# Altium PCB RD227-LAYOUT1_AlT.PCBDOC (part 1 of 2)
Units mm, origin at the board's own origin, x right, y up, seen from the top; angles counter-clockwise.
Board outline 90 x 40 mm, 4 copper layers (TOP, Mid-Layer 1, Mid-Layer 2, BOTTOM), stack 0.711 mm thick; 157 components, 70 nets, 392 pads, 454 vias.
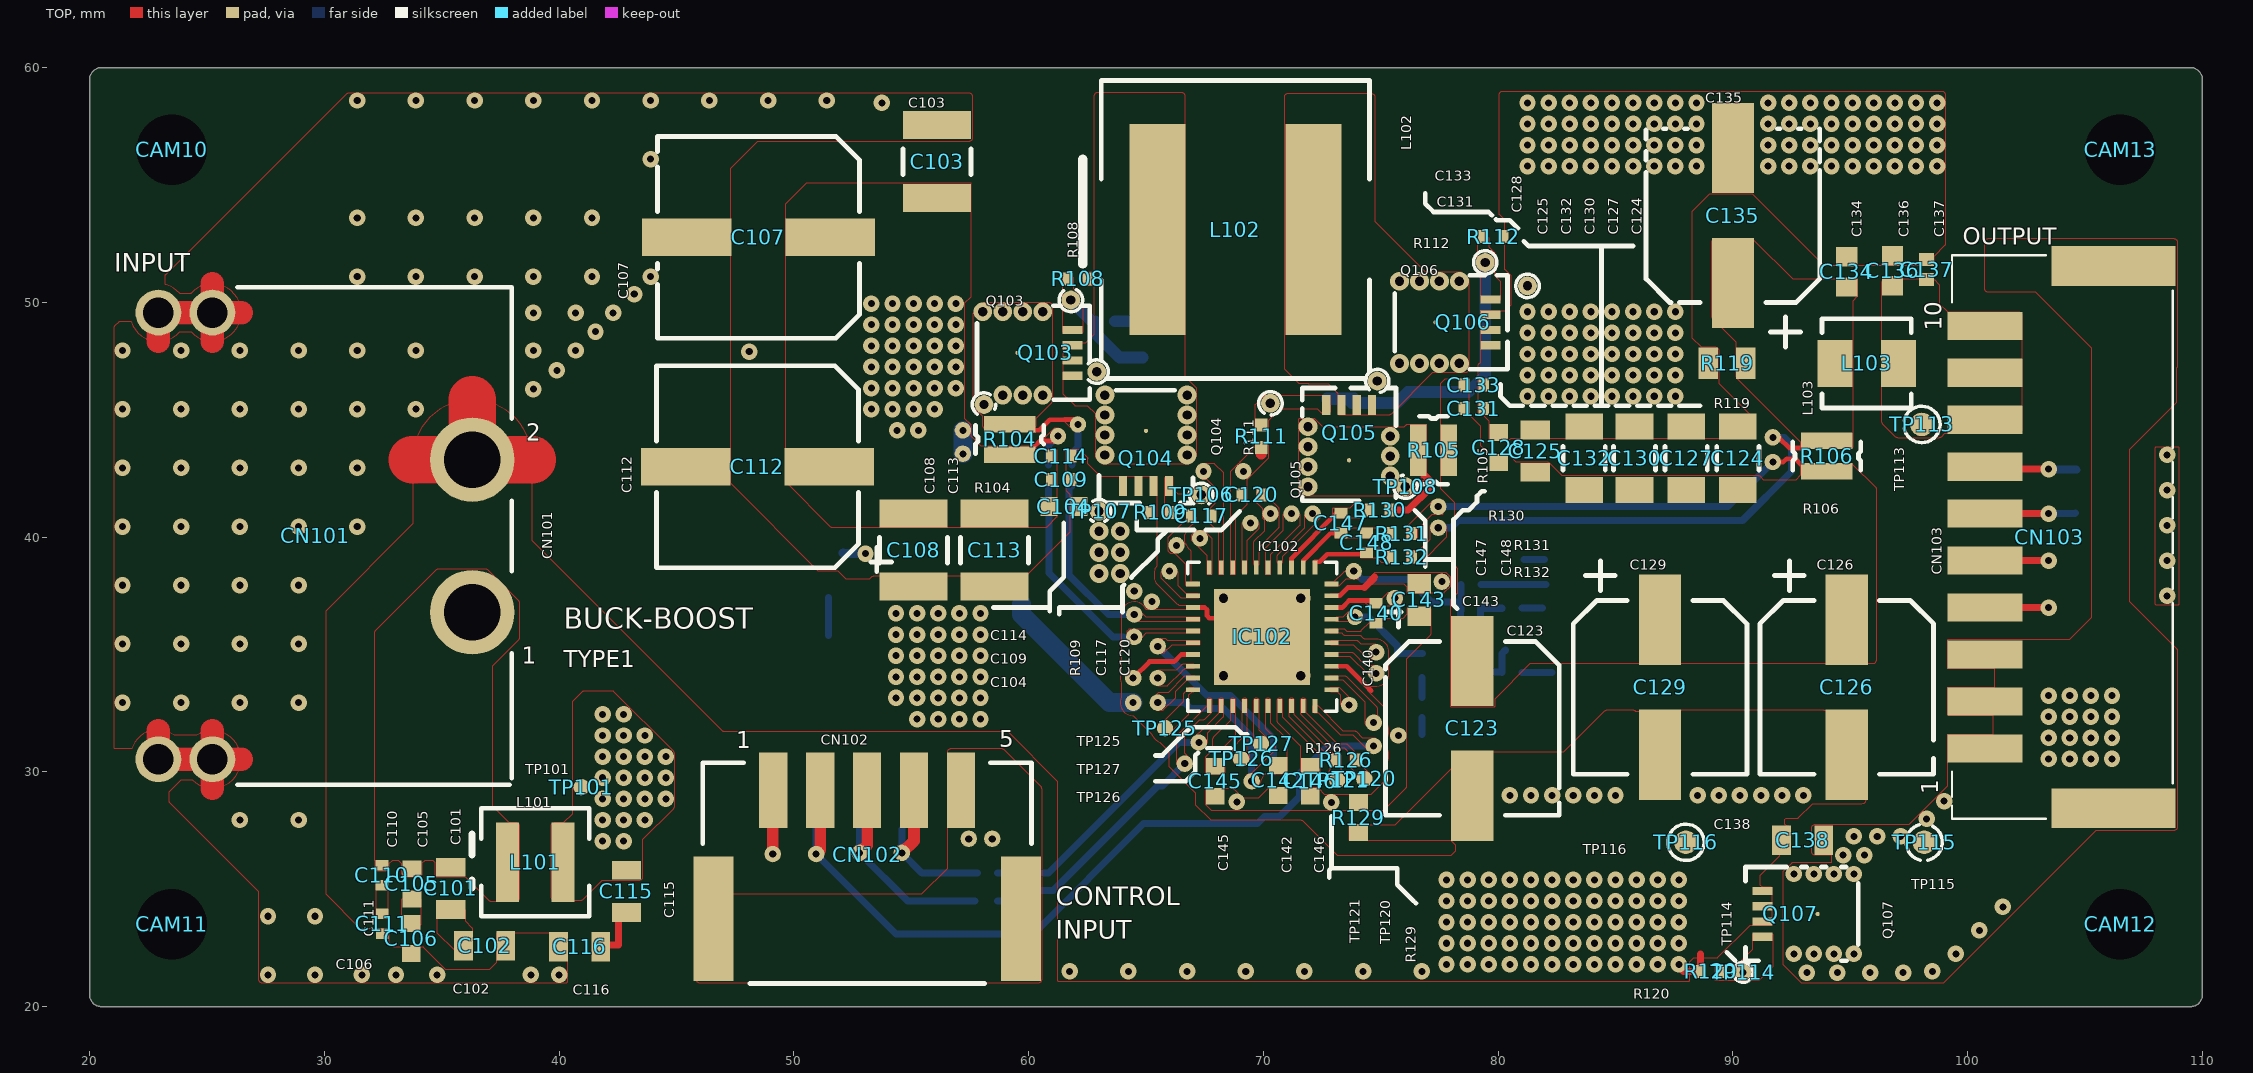
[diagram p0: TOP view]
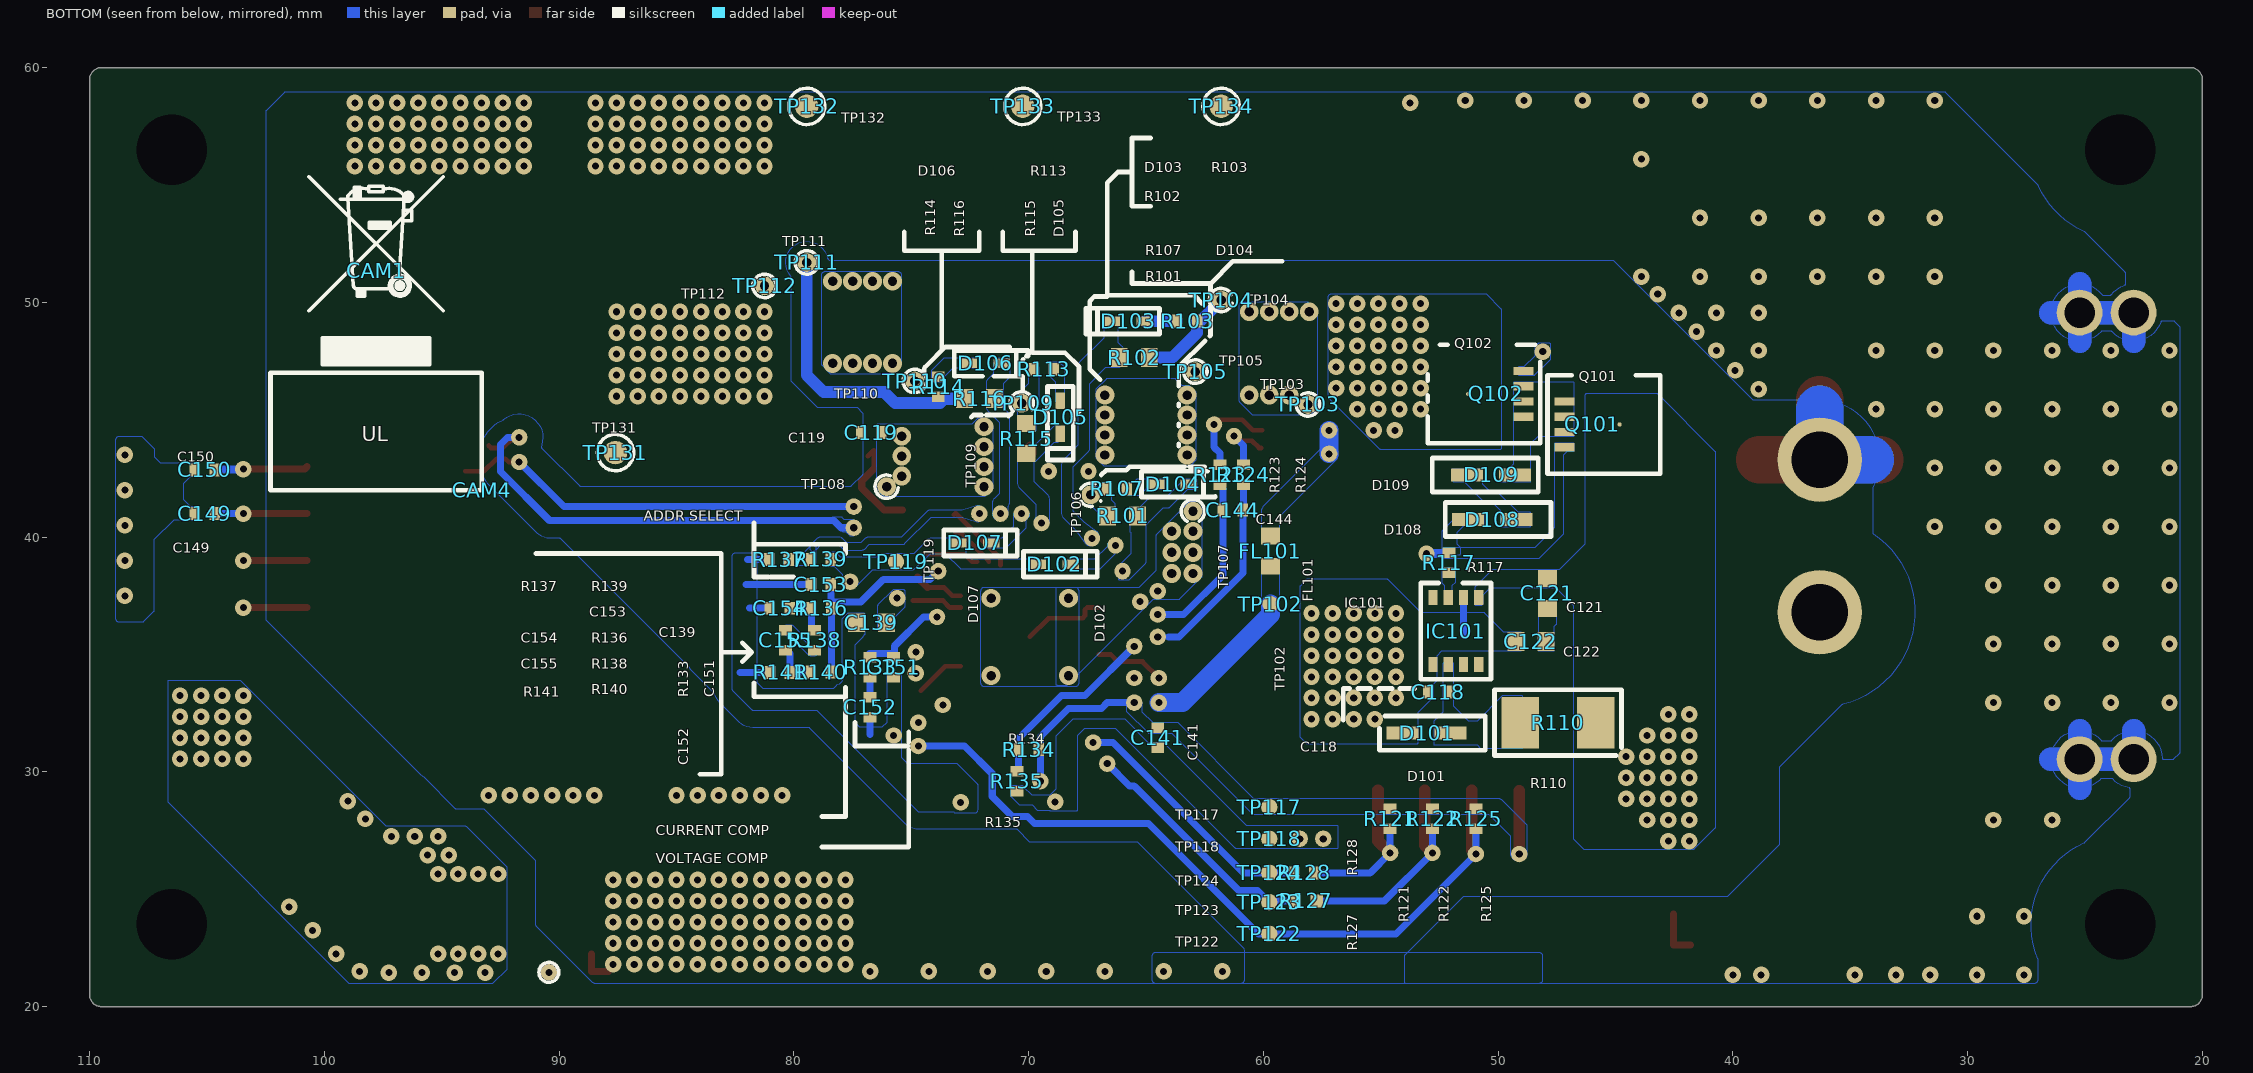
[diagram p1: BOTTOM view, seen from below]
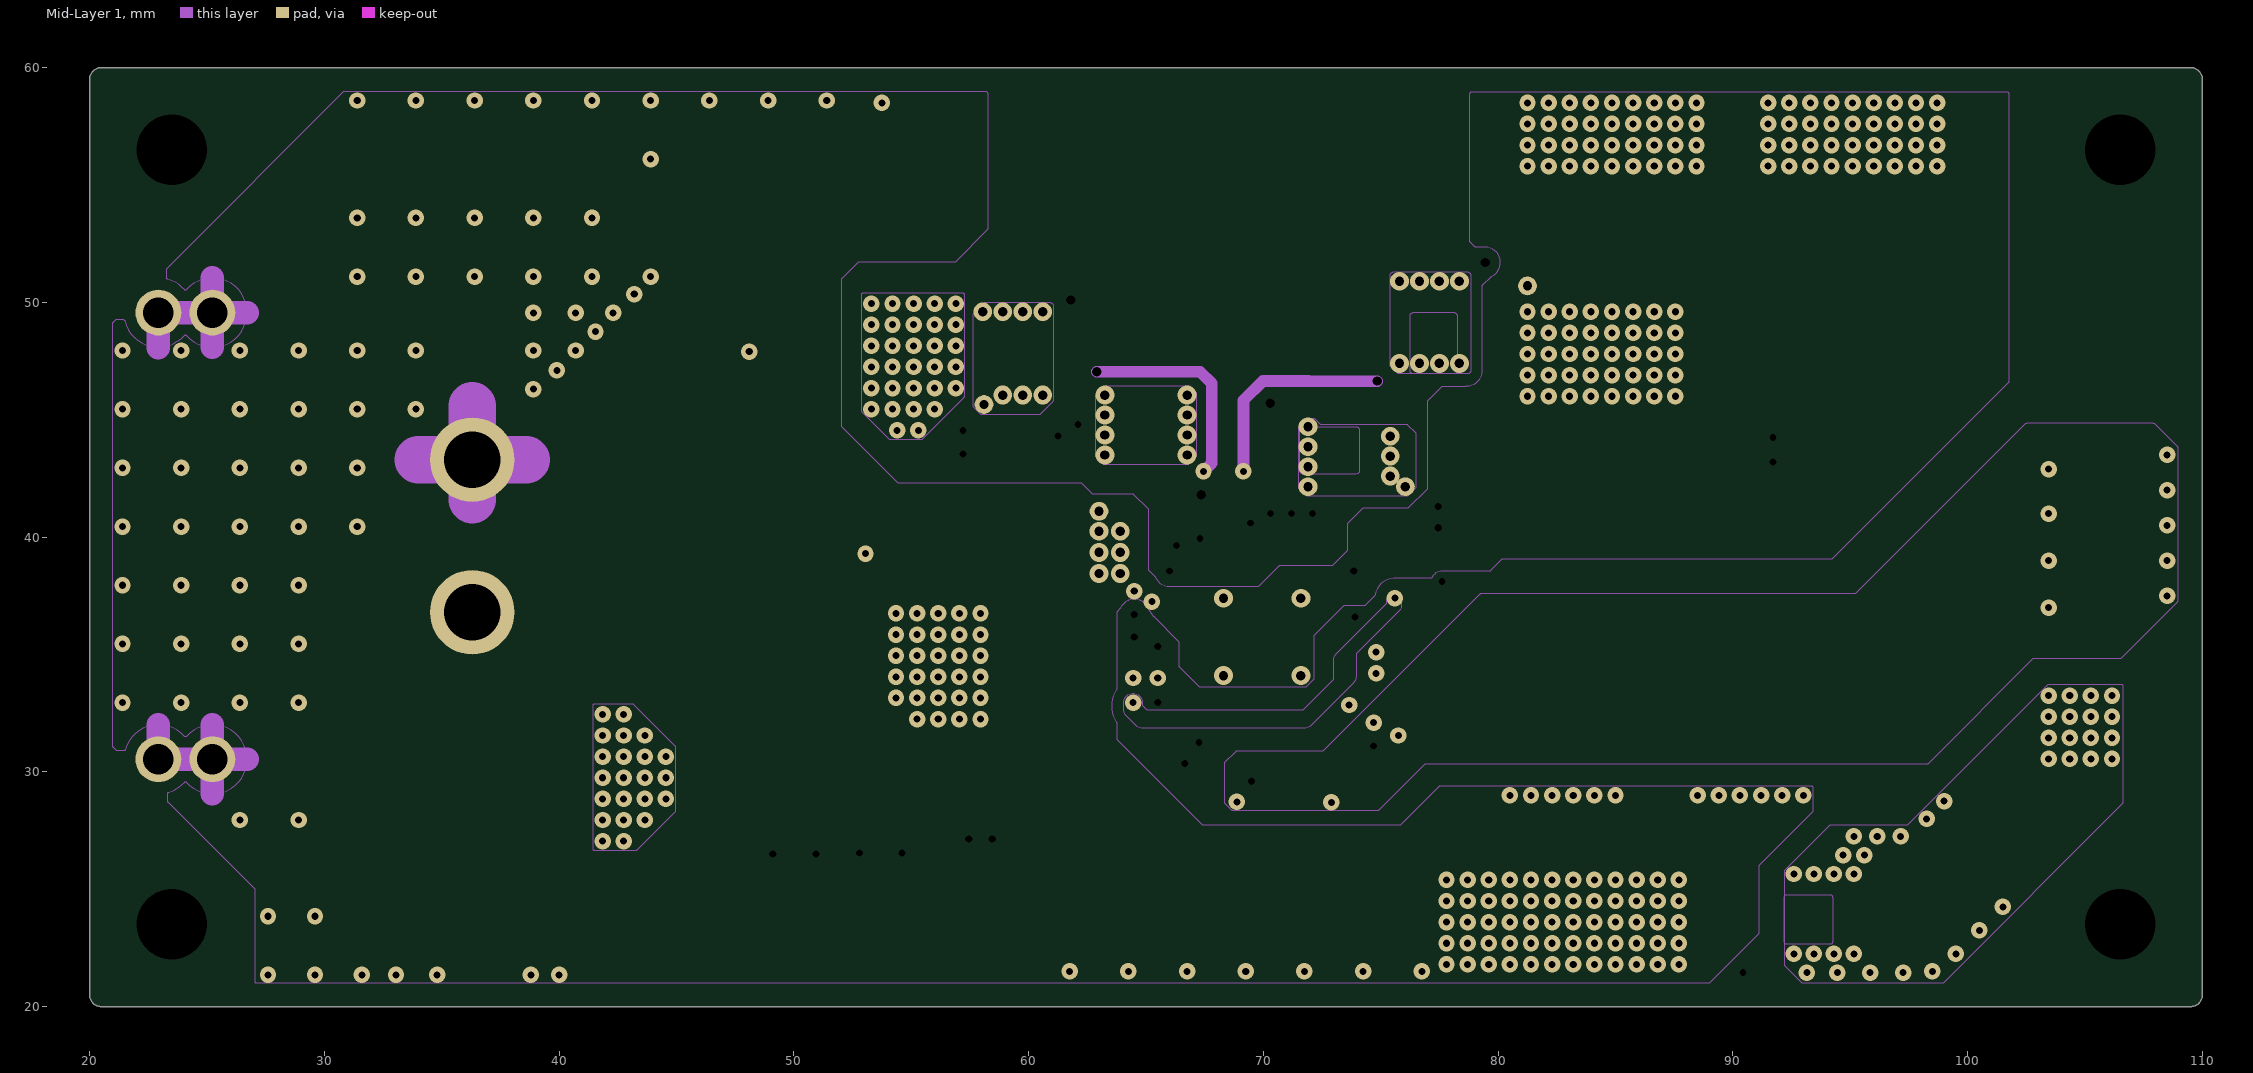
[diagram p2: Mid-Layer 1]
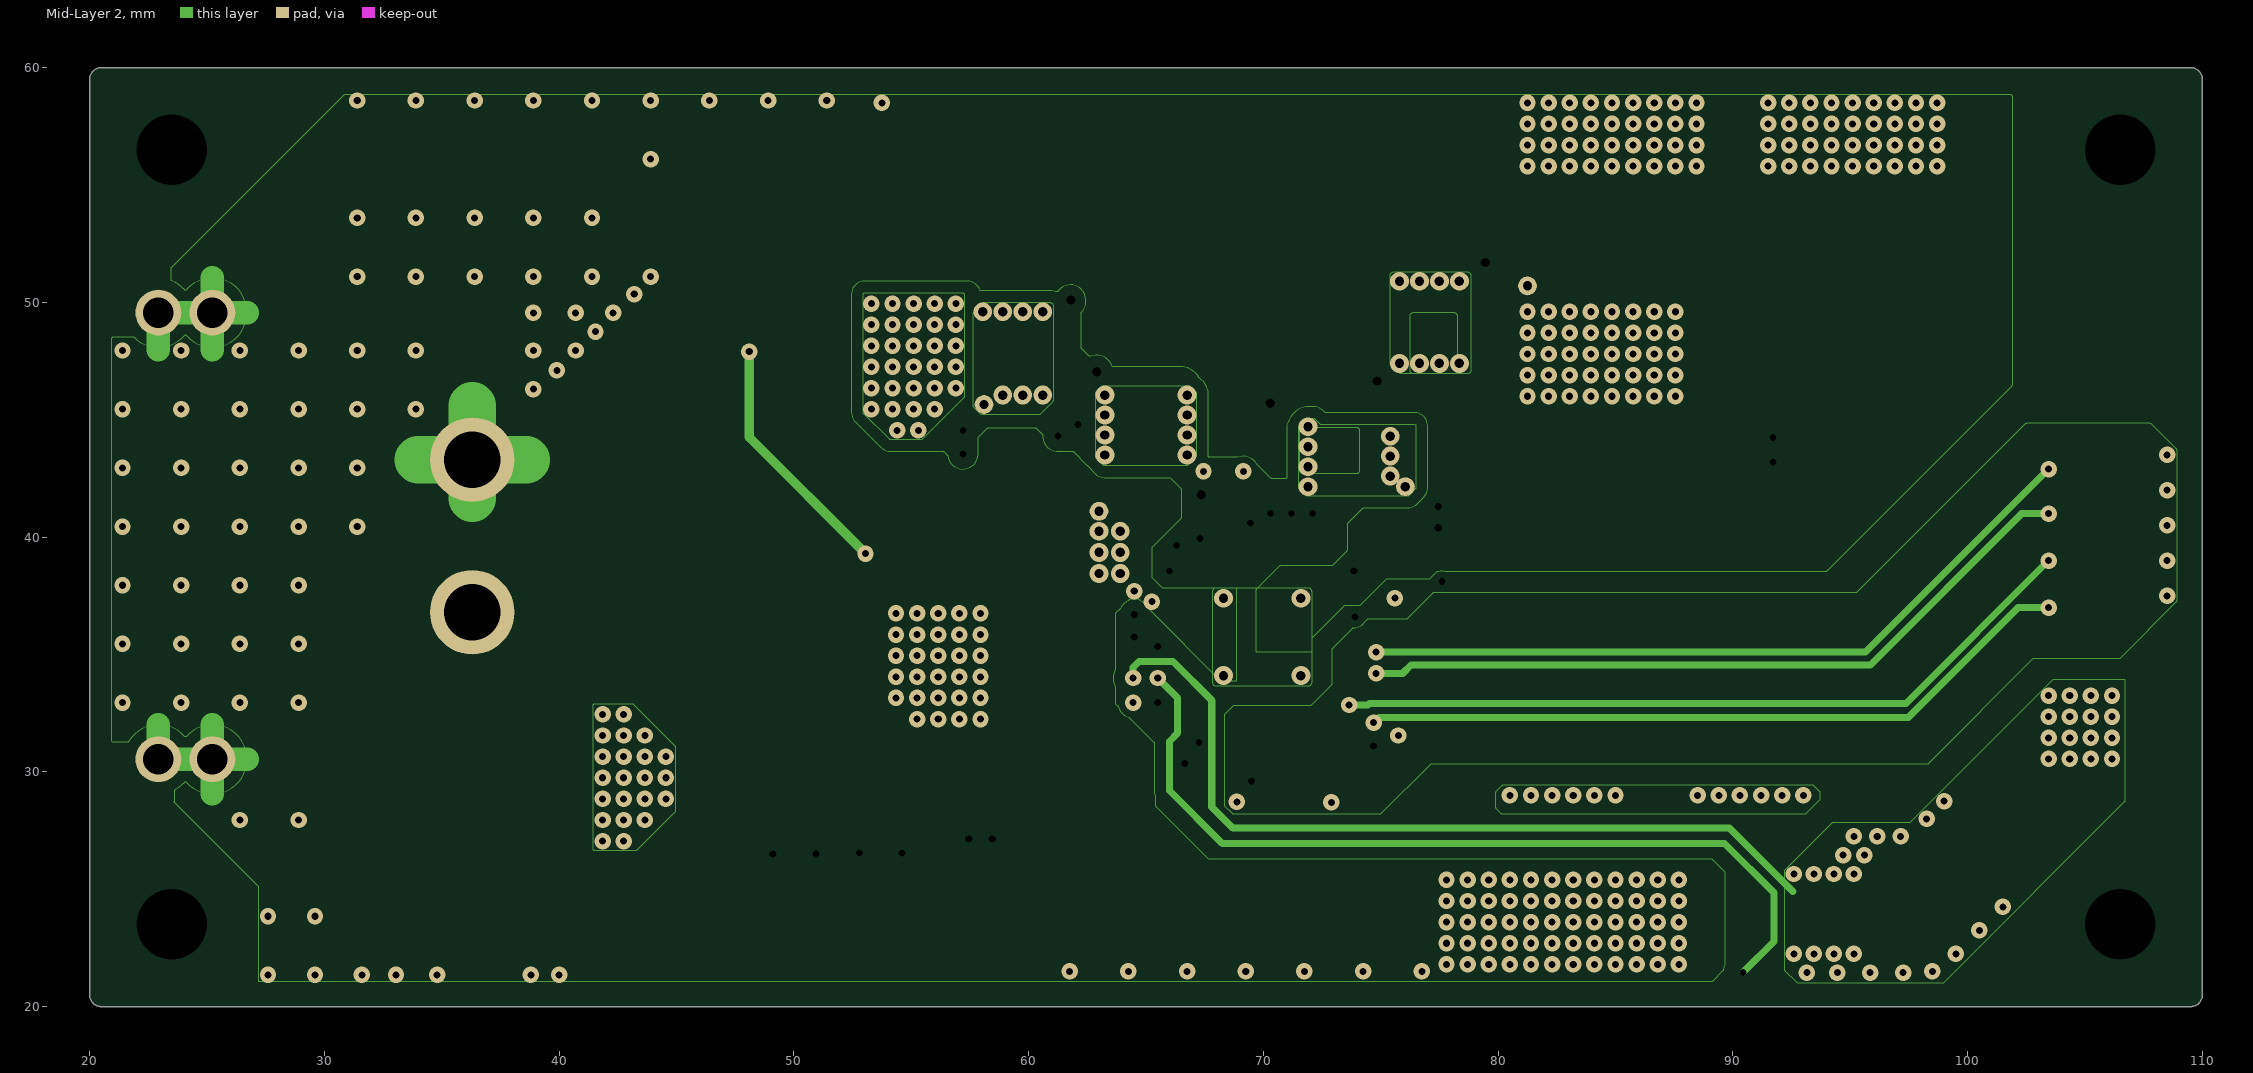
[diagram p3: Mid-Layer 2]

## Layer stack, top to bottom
Top Solder: solder mask 0.0102, Solder Resist, Dk 3.5
TOP: signal copper (thickness not stored)
Mid-Layer 1: signal copper 0.0356
Dielectric2: dielectric 0.32, FR-4, Dk 4.8
Mid-Layer 2: signal copper 0.0356
Dielectric3: dielectric 0.32, FR-4, Dk 4.8
BOTTOM: signal copper (thickness not stored)
Bottom Solder: solder mask 0.0102, Solder Resist, Dk 3.5

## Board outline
20,59.5 cw(c20.5,59.5) 20.5,60 109.5,60 cw(c109.5,59.5) 110,59.5 110,20.5 cw(c109.5,20.5) 109.5,20 20.5,20 cw(c20.5,20.5) 20,20.5

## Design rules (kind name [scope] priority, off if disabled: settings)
AssemblyTestPointUsage [All] p0: scope1count=1 scope1_0_kind=Board scope1_0_value=Board scope2count=1 scope2_0_kind=Board scope2_0_value=Board commentlength=0
AssemblyTestpoint [All] p0: scope1count=1 scope1_0_kind=Board scope1_0_value=Board scope2count=1 scope2_0_kind=Board scope2_0_value=Board commentlength=0
Clearance [All] p0: scope1count=1 scope1_0_kind=Board scope1_0_value=Board scope2count=1 scope2_0_kind=Board scope2_0_value=Board commentlength=0 gap=0.1
Clearance [All] p1: gap=0.1 ignorepadtopadclearanceinfootprint=TRUE except(0.11: SMDPad-Via; 0.15: SMDPad-SMDPad THPad-THPad Via-Via Via-Fill Via-Poly Via-Region; 0.25: SMDPad-Fill SMDPad-Poly SMDPad-Region THPad-Fill THPad-Poly THPad-Region Fill-Fill Fill-Poly Fill-Region Poly-Poly Poly-Region Region-Region; 1: Arc-Hole Track-Hole SMDPad-Hole THPad-Hole Fill-Hole Poly-Hole Region-Hole Text-Hole; 1.75: THPad-Via Via-Hole; 3: SMDPad-THPad)
ComponentClearance [All] p0: scope1count=1 scope1_0_kind=Board scope1_0_value=Board scope2count=1 scope2_0_kind=Board scope2_0_value=Board commentlength=0 gap=0.254 collisioncheckmode=3
DiffPairsRouting [All] p0: scope1count=1 scope1_0_kind=Board scope1_0_value=Board scope2count=1 scope2_0_kind=Board scope2_0_value=Board commentlength=0
FabricationTestPointUsage [All] p0: scope1count=1 scope1_0_kind=Board scope1_0_value=Board scope2count=1 scope2_0_kind=Board scope2_0_value=Board commentlength=0 valid=0 allowmultiple=FALSE
FabricationTestpoint [All] p0: scope1count=1 scope1_0_kind=Board scope1_0_value=Board scope2count=1 scope2_0_kind=Board scope2_0_value=Board commentlength=0 side=3 testpointundercomponent=TRUE minsize=1.016 maxsize=2.54 preferedsize=1.524 minholesize=0 maxholesize=1.016 preferedholesize=0.813 testpointgrid=0.025
FanoutControl Fanout_BGA [All] p0 off: scope1count=1 scope1_0_kind=Board scope1_0_value=Board scope2count=1 scope2_0_kind=Board scope2_0_value=Board commentlength=69 // Protel DXP Scope 1 Expression Was: IsBGA   Fanout_BGA (Default Rule)
FanoutControl Fanout_LCC [All] p0 off: scope1count=1 scope1_0_kind=Board scope1_0_value=Board scope2count=1 scope2_0_kind=Board scope2_0_value=Board commentlength=69 // Protel DXP Scope 1 Expression Was: IsLCC   Fanout_LCC (Default Rule)
FanoutControl Fanout_SOIC [All] p0 off: scope1count=1 scope1_0_kind=Board scope1_0_value=Board scope2count=1 scope2_0_kind=Board scope2_0_value=Board commentlength=71 // Protel DXP Scope 1 Expression Was: IsSOIC   Fanout_SOIC (Default Rule)
FanoutControl Fanout_Small [All] p0 off: scope1count=1 scope1_0_kind=Board scope1_0_value=Board scope2count=1 scope2_0_kind=Board scope2_0_value=Board commentlength=84 // Protel DXP Scope 1 Expression Was: (CompPinCount < 5)   Fanout_Small (Default Rule)
FanoutControl Fanout_Default [All] p0: scope1count=1 scope1_0_kind=Board scope1_0_value=Board scope2count=1 scope2_0_kind=Board scope2_0_value=Board commentlength=30 // Fanout_Default (Default Rule)
Height [All] p0: scope1count=1 scope1_0_kind=Board scope1_0_value=Board scope2count=1 scope2_0_kind=Board scope2_0_value=Board commentlength=0
HoleSize [All] p0: scope1count=1 scope1_0_kind=Board scope1_0_value=Board scope2count=1 scope2_0_kind=Board scope2_0_value=Board commentlength=0 absolutevalues=TRUE maxlimit=100 minlimit=0.001 maxpercent=80.000 minpercent=20.000
HoleSize [All] p1: absolutevalues=TRUE maxlimit=100 minlimit=0.001 maxpercent=80.000 minpercent=20.000
HoleToHoleClearance [All] p0: scope1count=1 scope1_0_kind=Board scope1_0_value=Board scope2count=1 scope2_0_kind=Board scope2_0_value=Board commentlength=0
HoleToHoleClearance [All] p1: gap=0.45 allowstackedmicrovias=FALSE
LayerPairs [All] p0: scope1count=1 scope1_0_kind=Board scope1_0_value=Board scope2count=1 scope2_0_kind=Board scope2_0_value=Board commentlength=0 enforce=TRUE
MinimumSolderMaskSliver [All] p0: scope1count=1 scope1_0_kind=Board scope1_0_value=Board scope2count=1 scope2_0_kind=Board scope2_0_value=Board commentlength=0
MinimumSolderMaskSliver [All] p1: minsoldermaskwidth=0.1
NetAntennae [All] p0: scope1count=1 scope1_0_kind=Board scope1_0_value=Board scope2count=1 scope2_0_kind=Board scope2_0_value=Board commentlength=0
NetAntennae [All] p1: netantennaetolerance=100
PasteMaskExpansion [All] p0: scope1count=1 scope1_0_kind=Board scope1_0_value=Board scope2count=1 scope2_0_kind=Board scope2_0_value=Board commentlength=0 expansion=0
PlaneClearance [All] p0: scope1count=1 scope1_0_kind=Board scope1_0_value=Board scope2count=1 scope2_0_kind=Board scope2_0_value=Board commentlength=0 clearance=0.001
PlaneClearance [All] p1: clearance=0.001
PlaneConnect [All] p0: scope1count=1 scope1_0_kind=Board scope1_0_value=Board scope2count=1 scope2_0_kind=Board scope2_0_value=Board commentlength=0 planeconnectstyle=Direct reliefexpansion=0.508 reliefentries=4 reliefconductorwidth=0.254 reliefairgap=0.254
PlaneConnect [All] p1: planeconnectstyle=Direct reliefexpansion=0.508 reliefentries=4 reliefconductorwidth=0.254 reliefairgap=0.254
PolygonConnect [All] p0: scope1count=1 scope1_0_kind=Board scope1_0_value=Board scope2count=1 scope2_0_kind=Board scope2_0_value=Board commentlength=0 connectstyle=Direct reliefconductorwidth=0.254 reliefentries=4 polygonreliefangle="90 Angle"
PolygonConnect [All] p1: connectstyle=Direct reliefconductorwidth=0.254 reliefentries=4 polygonreliefangle="90 Angle" airgapwidth=0.254
RoutingCorners [All] p0: scope1count=1 scope1_0_kind=Board scope1_0_value=Board scope2count=1 scope2_0_kind=Board scope2_0_value=Board commentlength=0 cornerstyle=45-Degree minsetback=2.54 maxsetback=2.54
RoutingLayers [All] p0: scope1count=1 scope1_0_kind=Board scope1_0_value=Board scope2count=1 scope2_0_kind=Board scope2_0_value=Board commentlength=0 top layer=Automatic mid layer 1=Automatic mid layer 2=Automatic bottom layer=Automatic
RoutingPriority [All] p0: scope1count=1 scope1_0_kind=Board scope1_0_value=Board scope2count=1 scope2_0_kind=Board scope2_0_value=Board commentlength=0
RoutingTopology [All] p0: scope1count=1 scope1_0_kind=Board scope1_0_value=Board scope2count=1 scope2_0_kind=Board scope2_0_value=Board commentlength=0 topology=Shortest
RoutingVias [All] p0: scope1count=1 scope1_0_kind=Board scope1_0_value=Board scope2count=1 scope2_0_kind=Board scope2_0_value=Board commentlength=0 holewidth=0.1 width=0.1 viastyle="Through Hole" minholewidth=0.001 minwidth=0.001 maxholewidth=100 maxwidth=100
RoutingVias [All] p1: holewidth=0.1 width=0.1 viastyle="Through Hole" minholewidth=0.001 minwidth=0.001 maxholewidth=100 maxwidth=100
ShortCircuit [All] p0: scope1count=1 scope1_0_kind=Board scope1_0_value=Board scope2count=1 scope2_0_kind=Board scope2_0_value=Board commentlength=0 allowed=FALSE
SilkToBoardRegionClearance [All] p0: scope1count=1 scope1_0_kind=Board scope1_0_value=Board scope2count=1 scope2_0_kind=Board scope2_0_value=Board commentlength=0
SilkToSilkClearance [All] p0: scope1count=1 scope1_0_kind=Board scope1_0_value=Board scope2count=1 scope2_0_kind=Board scope2_0_value=Board commentlength=0
SilkToSilkClearance [All] p1: silktosilkclearance=0.001
SilkToSolderMaskClearance [All] p0 off: scope1count=1 scope1_0_kind=Board scope1_0_value=Board scope2count=1 scope2_0_kind=Board scope2_0_value=Board commentlength=44 // Protel DXP Scope 1 Expression Was: IsPad
SilkToSolderMaskClearance [IsPad] p1: minsilkscreentomaskgap=0.11 clearancetoexposedcopper=TRUE
SolderMaskExpansion [All] p0: scope1count=1 scope1_0_kind=Board scope1_0_value=Board scope2count=1 scope2_0_kind=Board scope2_0_value=Board commentlength=0 expansion=0.001
SolderMaskExpansion [All] p1: expansion=0.001
UnRoutedNet [All] p0: scope1count=1 scope1_0_kind=Board scope1_0_value=Board scope2count=1 scope2_0_kind=Board scope2_0_value=Board commentlength=0
UnpouredPolygon [All] p0: scope1count=1 scope1_0_kind=Board scope1_0_value=Board scope2count=1 scope2_0_kind=Board scope2_0_value=Board commentlength=0
Width [All] p0: scope1count=1 scope1_0_kind=Board scope1_0_value=Board scope2count=1 scope2_0_kind=Board scope2_0_value=Board commentlength=0 maxlimit=1000 minlimit=2539.975 preferedwidth=0
Width [All] p1: maxlimit=1000 minlimit=2539.975 preferedwidth=0 toplayer_minwidth=0 midlayer1_minwidth=0 midlayer2_minwidth=0 bottomlayer_minwidth=0 minimp=50.000000 maximp=50.000000 favimp=50.000000
22 further rules are at their usual default settings.

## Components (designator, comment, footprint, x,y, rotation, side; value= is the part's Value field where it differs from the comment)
C101 "KC00060AKP" KC00060AKP 35.389,25.035 r90 top
C102 "KC00060AKP" KC00060AKP 36.828,22.597 r180 top
C103 "KCK03340AKP" KCK03340AKP 56.1,56 r270 top
C104 "KC00080AKP" KC00080AKP 61.5,41.3 r180 top
C105 "KC01340AKP" KC01340AKP 33.729,25.232 r90 top
C106 "KC01340AKP" KC01340AKP 33.7,22.9 r90 top
C107 "DC837K" DC837K 48.492,52.769 r0 top
C108 "KCK03340AKP" KCK03340AKP 55.1,39.45 r90 top
C109 "DC834K" DC834K 61.4,42.45 r180 top
C110 "DC834K" DC834K 32.45,25.6 r90 top
C111 "DC834K" DC834K 32.466,23.529 r90 top
C112 "DC837K" DC837K 48.45,43 r0 top
C113 "KCK03340AKP" KCK03340AKP 58.55,39.45 r90 top
C114 "DC834K" DC834K 61.4,43.45 r180 top
C115 "KC00060AKP" KC00060AKP 42.869,24.911 r90 top
C116 "KC00060AKP" KC00060AKP 40.874,22.545 r0 top
C117 "DC834K" DC834K 67.35,40.9 r0 top
C118 "DC934K" DC934K 52.55,33.4 r180 bottom
C119 "KC01540BKP01" KC01540BKP01 76.7,44.45 r0 bottom
C120 "DC834K" DC834K 69.5,41.8 r180 top
C121 "KC00080BKP" KC00080BKP 47.9,37.6 r90 bottom
C122 "KC00080BKP" KC00080BKP 48.6,35.55 r180 bottom
C123 "DC843R" DC843R 78.9,31.85 r90 top
C124 "KC00140AKP" KC00140AKP 90.209,43.364 r270 top
C125 "KC00060AKP" KC00060AKP 81.584,43.664 r270 top
C126 "DC843R" DC843R 94.85,33.6 r90 top
C127 "KC00140AKP" KC00140AKP 88.009,43.364 r270 top
C128 "KC00080AKP" KC00080AKP 80.023,43.816 r270 top
C129 "DC843R" DC843R 86.9,33.6 r90 top
C130 "KC00140AKP" KC00140AKP 85.809,43.364 r270 top
C131 "DC834K" DC834K 78.97,45.472 r180 top
C132 "KC00140AKP" KC00140AKP 83.659,43.364 r270 top
C133 "DC834K" DC834K 78.97,46.472 r180 top
C134 "KCK02380AKP01" KCK02380AKP01 94.85,51.3 r270 top
C135 "DC843R" DC843R 90,53.7 r270 top
C136 "KCK02380AKP01" KCK02380AKP01 96.8,51.35 r270 top
C137 "KC01540AKP" KC01540AKP 98.25,51.4 r270 top
C138 "KC00060AKP" KC00060AKP 92.966,27.09 r0 top
C139 "KC00080BKP" KC00080BKP 76.7,36.35 r180 bottom
C140 "DC834K" DC834K 74.8,36.75 r90 top
C141 "DC934K" DC934K 64.5,31.45 r90 bottom
C142 "KC01670AKP" KC01670AKP 70.631,29.633 r270 top
C143 "KC01560AKP" KC01560AKP 76.631,37.328 r270 top
C144 "DC934K" DC934K 61.3,41.15 r0 bottom
C145 "KC00080AKP" KC00080AKP 67.95,29.6 r270 top
C146 "KC00080AKP" KC00080AKP 72,29.6 r270 top
C147 "DC834K" DC834K 73.3,40.6 r90 top
C148 "DC834K" DC834K 74.4,39.75 r90 top
C149 "DC934K" DC934K 105.1,41 r180 bottom
C150 "DC934K" DC934K 105.092,42.864 r180 bottom
C151 "DC934K" DC934K 75.75,34.45 r90 bottom
C152 "DC934K" DC934K 76.75,32.75 r90 bottom
C153 "DC934K" DC934K 78.845,37.981 r180 bottom
C154 "DC934K" DC934K 80.599,36.972 r180 bottom
C155 "DC934K" DC934K 80.35,35.6 r90 bottom
CAM1 "CAM_LOGO_MARK_WEEE-B" CAM_LOGO_MARK_WEEE-B 97.8,51.35 r0 bottom
CAM4 "Local_ULCMN-B" Local_ULCMN-B 93.3,42 r0 bottom
CAM10 "NTC300" NTC300 23.5,56.5 r0 top
CAM11 "NTC300" NTC300 23.5,23.5 r0 top
CAM12 "NTC300" NTC300 106.5,23.5 r0 top
CAM13 "NTC300" NTC300 106.5,56.5 r0 top
CN101 "Local_HVH-280-2P-6_5DS" Local_HVH-280-2P-6_5DS 36.3,36.8 r270 top
CN102 "Local_502352-0501" Local_502352-0501 53.121,25.687 r0 top
CN103 "Local_502352-1000" Local_502352-1000 104,40 r90 top
D101 "D9K022" D9K022 53.05,31.65 r0 bottom
D102 "D8101D1BKP" D8101D1BKP 68.9,38.85 r0 bottom
D103 "D8101D1BKP" D8101D1BKP 65.75,49.2 r180 bottom
D104 "D8101D1BKP" D8101D1BKP 63.87,42.26 r0 bottom
D105 "D8101D1BKP" D8101D1BKP 68.65,45.1 r90 bottom
D106 "D8101D1BKP" D8101D1BKP 71.85,47.4 r0 bottom
D107 "D8101D1BKP" D8101D1BKP 72.3,39.75 r0 bottom
D108 "D9K022" D9K022 50.25,40.75 r0 bottom
D109 "D9K022" D9K022 50.3,42.65 r180 bottom
FL101 "KC00080BKP" KC00080BKP 59.7,39.4 r270 bottom
IC101 "SN00281BKP" SN00281BKP 51.8,36 r180 bottom
IC102 "Local_MAX25432BATLGV+-A" Local_MAX25432BATLGV+-A 69.95,35.75 r0 top
L101 "Local_XEL-4030-471MEC" Local_XEL-4030-471MEC 38.984,26.149 r0 top
L102 "Local_XAL1010-472MED" Local_XAL1010-472MED 68.811,53.102 r0 top
L103 "Local_IHLP1212BZEVR22M5A" Local_IHLP1212BZEVR22M5A 95.7,47.4 r0 top
Q101 "SN00612BKP" SN00612BKP 45.5,44.8 r90 bottom
Q102 "SN00612BKP" SN00612BKP 50.6,46.1 r270 bottom
Q103 "SN00612AKP" SN00612AKP 60.2,47.85 r90 top
Q104 "SN00612AKP" SN00612AKP 65,43.85 r0 top
Q105 "SN00612AKP" SN00612AKP 73.65,43.95 r180 top
Q106 "SN00612AKP" SN00612AKP 78,49.15 r90 top
Q107 "SN00612AKP" SN00612AKP 92.935,23.948 r270 top
R101 "KC00080BKP" KC00080BKP 66,40.9 r180 bottom
R102 "KC00080BKP" KC00080BKP 65.5,47.65 r0 bottom
R103 "DC934K" DC934K 63.25,49.2 r0 bottom
R104 "Local_KRL2012" Local_KRL2012 59.19,44.166 r90 top
R105 "Local_KRL2012" Local_KRL2012 77.25,43.7 r0 top
R106 "Local_KRL2012" Local_KRL2012 94,43.45 r90 top
R107 "DC934K" DC934K 66.24,42.05 r180 bottom
R108 "DR824K" DR824K 62.1,51 r180 top
R109 "DR824K" DR824K 65.6,41.05 r0 top
R110 "DR901RF" DR901RF 47.45,32.1 r180 bottom
R111 "KC01310AKP" KC01310AKP 69.91,44.292 r90 top
R112 "DR824K" DR824K 79.8,52.8 r180 top
R113 "DC934K" DC934K 69.35,47.15 r180 bottom
R114 "DC934K" DC934K 73.85,46.4 r90 bottom
R115 "KC00080BKP" KC00080BKP 70.1,44.2 r270 bottom
R116 "KC00080BKP" KC00080BKP 72.1,45.9 r180 bottom
R117 "DR924K" DR924K 52.1,38.9 r90 bottom
R119 "DR810K" DR810K 89.75,47.4 r0 top
R120 "DR824K" DR824K 89.051,21.503 r0 top
R121 "DR924K" DR924K 54.6,28 r270 bottom
R122 "DR924K" DR924K 52.8,28 r270 bottom
R123 "DC934K" DC934K 61.85,42.65 r90 bottom
R124 "DC934K" DC934K 60.85,42.65 r90 bottom
R125 "DR924K" DR924K 50.95,28 r270 bottom
R126 "DR824K" DR824K 73.5,30.5 r180 top
R127 "KC01310BKP" KC01310BKP 58.2,24.5 r180 bottom
R128 "DR924K" DR924K 58.25,25.7 r180 bottom
R129 "KC00080AKP" KC00080AKP 74.05,28.05 r90 top
R130 "DR824K" DR824K 74.95,41.15 r180 top
R131 "DR824K" DR824K 75.9,40.15 r180 top
R132 "DR824K" DR824K 75.9,39.15 r180 top
R133 "DR924K" DR924K 76.75,34.45 r90 bottom
R134 "DR924K" DR924K 70,30.95 r0 bottom
R135 "DR924K" DR924K 70.5,29.6 r270 bottom
R136 "KC00050BKP" KC00050BKP 78.829,36.97 r180 bottom
R137 "DR924K" DR924K 80.635,39.039 r0 bottom
R138 "DR924K" DR924K 79.113,35.602 r90 bottom
R139 "DR924K" DR924K 78.85,39.05 r0 bottom
R140 "DR924K" DR924K 78.85,34.251 r180 bottom
R141 "DR924K" DR924K 80.592,34.24 r180 bottom
TP101 "TL0.7_A_noMM" TL0.7_A_noMM 40.95,29.35 r0 top
TP102 "TL0.7_B_noMM" TL0.7_B_noMM 59.7,37.15 r0 bottom
TP103 "Local_TL0.4_TH-B" Local_TL0.4_TH-B#1 58.1,45.65 r0 bottom
TP104 "Local_TL0.4_TH-B" Local_TL0.4_TH-B#2 61.8,50.1 r0 bottom
TP105 "Local_TL0.4_TH-B" Local_TL0.4_TH-B#2 62.9,47.05 r0 bottom
TP106 "Local_TL0.4_TH-A" Local_TL0.4_TH-A#1 67.35,41.8 r0 top
TP107 "Local_TL0.4_TH-A" Local_TL0.4_TH-A#2 63,41.1 r0 top
TP108 "Local_TL0.4_TH-A" Local_TL0.4_TH-A#2 76.05,42.15 r0 top
TP109 "Local_TL0.4_TH-B" Local_TL0.4_TH-B#2 70.3,45.7 r0 bottom
TP110 "Local_TL0.4_TH-B" Local_TL0.4_TH-B#2 74.85,46.65 r0 bottom
TP111 "Local_TL0.4_TH-B" Local_TL0.4_TH-B#2 79.45,51.7 r0 bottom
TP112 "Local_TL0.4_TH-B" Local_TL0.4_TH-B#1 81.25,50.7 r0 bottom
TP113 "Local_TP-100-A" Local_TP-100-A 98.05,44.8 r0 top
TP114 "Local_TL0.3_TH-A" Local_TL0.3_TH-A 90.437,21.463 r0 top
TP115 "Local_TP-100-A" Local_TP-100-A 98.15,27 r0 top
TP116 "Local_TP-100-A" Local_TP-100-A 88,27 r0 top
TP117 "TL0.7_B_noMM" TL0.7_B_noMM 59.75,28.5 r0 bottom
TP118 "TL0.7_B_noMM" TL0.7_B_noMM 59.75,27.15 r0 bottom
TP119 "TL0.7_B_noMM" TL0.7_B_noMM 75.65,38.95 r0 bottom
TP120 "TL0.7_A_noMM" TL0.7_A_noMM 74.3,29.7 r0 top
TP121 "TL0.7_A_noMM" TL0.7_A_noMM 73.15,29.65 r0 top
TP122 "TL0.7_B_noMM" TL0.7_B_noMM 59.75,23.1 r0 bottom
TP123 "TL0.7_B_noMM" TL0.7_B_noMM 59.75,24.45 r0 bottom
TP124 "TL0.7_B_noMM" TL0.7_B_noMM 59.75,25.7 r0 bottom
TP125 "TL0.7_A_noMM" TL0.7_A_noMM 65.808,31.864 r0 top
TP126 "TL0.7_A_noMM" TL0.7_A_noMM 69.05,30.55 r0 top
TP127 "TL0.7_A_noMM" TL0.7_A_noMM 69.9,31.2 r0 top
TP131 "Local_TP-100-B" Local_TP-100-B 87.6,43.6 r0 bottom
TP132 "Local_TP-100-B" Local_TP-100-B 79.45,58.35 r0 bottom
TP133 "Local_TP-100-B" Local_TP-100-B 70.25,58.35 r0 bottom
TP134 "Local_TP-100-B" Local_TP-100-B 61.8,58.35 r0 bottom

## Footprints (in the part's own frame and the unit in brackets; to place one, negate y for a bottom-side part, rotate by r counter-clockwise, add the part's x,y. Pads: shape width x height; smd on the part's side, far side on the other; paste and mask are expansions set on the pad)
CAM_LOGO_MARK_WEEE-B [mm] "KC00080BKP"
  silkscreen extent -2.86,-4 2.86,4
D9K022 [mm] "KC00080BKP"
  rect 1.36x0.55 smd paste-1.36 mask+0: A(1.025,0) C(-1.025,0)
  silkscreen extent -2.51,-0.72 2,0.72
D8101D1BKP [mm] "KC00080BKP"
  rect 0.7x0.4 smd paste-0.7 mask+0: A(0.7,0) C(-0.7,0)
  silkscreen extent -1.82,-0.55 1.32,0.55
DC834K [mm] "KC00080BKP"
  rect 0.45x0.55 smd paste-0.55 mask+0: 1(-0.425,0) 2(0.425,0)
DC837K [mm] "KC00080BKP"
  rect 3.82x1.6 smd paste-3.82 mask+0: 1(-3.06,0) 2(3.06,0)
  silkscreen extent -4.3,-4.3 4.3,4.3
DC843R [mm] "KC00080BKP"
  rect 3.85x1.8 smd paste-3.85 mask+0: 1(-2.875,0) 2(2.875,0)
  silkscreen extent -3.7,-3.7 5.14,3.7
DC934K [mm] "KC00080BKP"
  rect 0.45x0.55 smd paste-0.55 mask+0: 1(-0.425,0) 2(0.425,0)
DR810K [mm] "KC00080BKP"
  rect 0.83x1.35 smd paste-1.35 mask+0: 1(-0.8,0) 2(0.8,0)
DR824K [mm] "KC00080BKP"
  rect 0.45x0.55 smd paste-0.55 mask+0: 1(-0.425,0) 2(0.425,0)
DR901RF [mm] "KC00080BKP"
  rect 1.6x2.2 smd paste-2.2 mask+0: 1(-1.6,0) 2(1.6,0)
  silkscreen extent -2.7,-1.4 2.7,1.4
DR924K [mm] "KC00080BKP"
  rect 0.45x0.55 smd paste-0.55 mask+0: 1(-0.425,0) 2(0.425,0)
KC00050BKP [mm] "KC00080BKP"
  rect 0.45x0.55 smd paste-0.55 mask+0: 1(-0.425,0) 2(0.425,0)
KC00060AKP [mm] "KC00080BKP"
  rect 0.8x1.25 smd paste-1.25 mask+0: 1(-0.9,0) 2(0.9,0)
KC00080AKP [mm] "KC00080BKP"
  rect 0.72x0.8 smd paste-0.8 mask+0: 1(-0.64,0) 2(0.64,0)
KC00080BKP [mm] "KC00080BKP"
  rect 0.72x0.8 smd paste-0.8 mask+0: 1(-0.64,0) 2(0.64,0)
KC00140AKP [mm] "KC00080BKP"
  rect 1.1x1.6 smd paste-1.6 mask+0: 1(-1.35,0) 2(1.35,0)
  silkscreen extent -0.5,-0.9 0.5,0.9
KC01310AKP [mm] "KC00080BKP"
  rect 0.55x0.55 smd paste-0.55 mask+0: 1(-0.475,0) 2(0.475,0)
KC01310BKP [mm] "KC00080BKP"
  rect 0.55x0.55 smd paste-0.55 mask+0: 1(-0.475,0) 2(0.475,0)
KC01340AKP [mm] "KC00080BKP"
  rect 0.72x0.8 smd paste-0.8 mask+0: 1(-0.64,0) 2(0.64,0)
KC01540AKP [mm] "KC00080BKP"
  rect 0.55x0.65 smd paste-0.65 mask+0: 1(-0.425,0) 2(0.425,0)
KC01540BKP01 [mm] "KC00080BKP"
  rect 0.45x0.55 smd paste-0.55 mask+0: 1(-0.425,0) 2(0.425,0)
KC01560AKP [mm] "KC00080BKP"
  rect 0.83x1 smd paste-1 mask+0: 1(-0.695,0) 2(0.695,0)
KC01670AKP [mm] "KC00080BKP"
  rect 0.72x0.8 smd paste-0.8 mask+0: 1(-0.64,0) 2(0.64,0)
KCK02380AKP01 [mm] "KC00080BKP"
  rect 0.82x0.9 smd paste-0.9 mask+0: 1(-0.64,0) 2(0.64,0)
KCK03340AKP [mm] "KC00080BKP"
  rect 1.2x2.9 smd paste-2.9 mask+0: 1(-1.55,0) 2(1.55,0)
  silkscreen extent -0.55,-1.45 0.55,1.45
Local_502352-0501 [mm] "KC00080BKP"
  rect 1.2x3.2 smd paste-3.2 mask+0: 1(-4,3.53) 2(-2,3.53) 3(0,3.53) 4(2,3.53) 5(4,3.53)
  rect 1.7x5.3 smd paste-5.3 mask+0: 1T(-6.55,-1.95) 2T(6.55,-1.95)
  silkscreen extent -7,-4.7 7,4.7
Local_502352-1000 [mm] "KC00080BKP"
  rect 1.2x3.2 smd paste-3.2 mask+0: 1(-9,3.265) 2(-7,3.265) 3(-5,3.265) 4(-3,3.265) 5(-1,3.265) 6(1,3.265) 7(3,3.265) 8(5,3.265) 9(7,3.265) 10(9,3.265)
  rect 1.7x5.3 smd paste-5.3 mask+0: 1T(-11.55,-2.215) 2T(11.55,-2.215)
  silkscreen extent -12,-4.73 12,4.66
Local_HVH-280-2P-6_5DS [mm] "KC00080BKP"
  round 3.6 hole 2.4 paste-3.6 mask+0: 1(0,0) 2(-6.5,0)
  round 1.95 hole 1.3 paste-1.95 mask+0: 1T(6.265,-13.37) 2T(6.265,-11.07) 3T(-12.765,-11.07) 4T(-12.765,-13.37)
  silkscreen extent -13.85,-10 7.35,1.68
Local_IHLP1212BZEVR22M5A [mm] "KC00080BKP"
  rect 1.5x2 smd paste-2 mask+0: 1(-1.35,0) 2(1.35,0)
  silkscreen extent -1.9,-1.9 1.9,1.9
Local_KRL2012 [mm] "KC00080BKP"
  rect 0.7x2.2 smd paste-2.2 mask+0: 1(-0.65,0) 2(0.65,0)
  silkscreen extent -0.6,-1.45 0.6,1.45
Local_MAX25432BATLGV+-A [mm] "KC00080BKP"
  rect 0.6x0.2 smd paste-0.6 mask+0: 1(-2.948,2.25) 2(-2.948,1.75) 3(-2.948,1.25) 4(-2.948,0.75) 5(-2.948,0.25) 6(-2.948,-0.25) 7(-2.948,-0.75) 8(-2.948,-1.25) 9(-2.948,-1.75) 10(-2.948,-2.25) 21(2.948,-2.25) 22(2.948,-1.75) 23(2.948,-1.25) 24(2.948,-0.75) 25(2.948,-0.25) 26(2.948,0.25) 27(2.948,0.75) 28(2.948,1.25) 29(2.948,1.75) 30(2.948,2.25)
  rect 0.2x0.6 smd paste-0.6 mask+0: 11(-2.25,-2.948) 12(-1.75,-2.948) 13(-1.25,-2.948) 14(-0.75,-2.948) 15(-0.25,-2.948) 16(0.25,-2.948) 17(0.75,-2.948) 18(1.25,-2.948) 19(1.75,-2.948) 20(2.25,-2.948) 31(2.25,2.948) 32(1.75,2.948) 33(1.25,2.948) 34(0.75,2.948) 35(0.25,2.948) 36(-0.25,2.948) 37(-0.75,2.948) 38(-1.25,2.948) 39(-1.75,2.948) 40(-2.25,2.948)
  rect 4.089x4.089 smd paste-4.089 mask+0: 41(0,0)
  silkscreen extent -3.17,-3.17 3.17,3.17
Local_TL0.3_TH-A [mm] "KC00080BKP"
  round 0.7 / inner round 0 / far side round 0.7 hole 0.3 paste-0.7 mask+0: 1(0,0)
  silkscreen extent -0.42,-0.42 0.43,0.42
Local_TL0.4_TH-A#1 [mm] "KC00080BKP"
  round 0.8 / inner round 0 / far side round 0.8 hole 0.4 paste-0.8 mask+0: 1(0,0)
  silkscreen extent -0.5,-0.39 0.5,0.5
Local_TL0.4_TH-A#2 [mm] "KC00080BKP"
  round 0.8 hole 0.4 paste-0.8 mask+0: 1(0,0)
  silkscreen extent -0.35,-0.43 0.5,0.5
Local_TL0.4_TH-B#1 [mm] "KC00080BKP"
  round 0.8 hole 0.4 paste-0.8 mask+0: 1(0,0)
  silkscreen extent -0.5,-0.5 0.5,0.5
Local_TL0.4_TH-B#2 [mm] "KC00080BKP"
  round 0.8 / inner round 0 / far side round 0.8 hole 0.4 paste-0.8 mask+0: 1(0,0)
  silkscreen extent -0.48,-0.5 0.5,0.5
Local_TP-100-A [mm] "KC00080BKP"
  round 1 smd paste-1 mask+0: 1(0,0)
  silkscreen extent -0.76,-0.77 0.77,0.77
Local_TP-100-B [mm] "KC00080BKP"
  round 1 smd paste-1 mask+0: 1(0,0)
  silkscreen extent -0.77,-0.77 0.77,0.77
Local_ULCMN-B [mm] "KC00080BKP"
  silkscreen extent 0,-5 9,0
Local_XAL1010-472MED [mm] "KC00080BKP"
  rect 2.38x9 smd paste-9 mask+0: 1(-3.325,0) 2(3.325,0)
  silkscreen extent -6.5,-6.35 5.71,6.35
Local_XEL-4030-471MEC [mm] "KC00080BKP"
  rect 0.98x3.4 smd paste-3.4 mask+0: 1(-1.185,0) 2(1.185,0)
  silkscreen extent -2.7,-2.3 2.3,2.3
NTC300 [mm] "KC00080BKP"
  round 0 hole 3 unplated paste-3.5 mask+0: ""(0,0)
SN00281BKP [mm] "KC00080BKP"
  rect 0.4x0.65 smd paste-0.65 mask+0: 1(0.975,1.425) 2(0.325,1.425) 3(-0.325,1.425) 4(-0.975,1.425) 5(-0.975,-1.425) 6(-0.325,-1.425) 7(0.325,-1.425) 8(0.975,-1.425)
  silkscreen extent -1.5,-2.05 1.5,2.05
SN00612AKP [mm] "KC00080BKP"
  rect 0.35x0.85 smd paste-0.85 mask+0: 1(-0.975,-1.675) 2(-0.325,-1.675) 3(0.325,-1.675) 4(0.975,-1.675)
  round 0.178 smd paste-0.178 mask+0: 5(0,0.675)
  silkscreen extent -2,-2.4 2,2.4
SN00612BKP [mm] "KC00080BKP"
  rect 0.35x0.85 smd paste-0.85 mask+0: 1(0.975,1.675) 2(0.325,1.675) 3(-0.325,1.675) 4(-0.975,1.675)
  round 0.178 smd paste-0.178 mask+0: 5(0,-0.675)
  silkscreen extent -2.1,-2.4 2.1,2.4
TL0.7_A_noMM [mm] "KC00080BKP"
  round 0.7 smd paste-0.8 mask+0: 1(0,0)
TL0.7_B_noMM [mm] "KC00080BKP"
  round 0.7 smd paste-0.8 mask+0: 1(0,0)

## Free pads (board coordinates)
  round 0.7 / inner round 0 / far side round 0.7 hole 0.3 paste-0.7 mask+0: ""(49.1,26.5) ""(50.95,26.5) ""(52.8,26.55) ""(54.6,26.55) ""(57.2,43.55) ""(57.2,44.55) ""(57.45,27.15) ""(58.45,27.15) ""(61.25,44.3) ""(62.1,44.8) ""(64.5,35.75) ""(64.5,36.7) ""(65.5,32.95) ""(65.5,35.35) ""(66,38.55) ""(66.3,39.65) ""(66.65,30.35) ""(67.25,31.25) ""(67.3,39.95) ""(69.45,40.6) ""(69.5,29.6) ""(70.3,41) ""(71.2,41) ""(72.1,41) ""(73.85,38.55) ""(73.9,36.6) ""(74.7,31.1) ""(77.45,40.4) ""(77.45,41.3) ""(77.6,38.1) ""(91.7,43.2) ""(91.7,44.25)

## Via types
v1: diameter 0.7, hole 0.3, TOP to BOTTOM, 414 vias
v2: diameter 0.8, hole 0.4, TOP to BOTTOM, 40 vias

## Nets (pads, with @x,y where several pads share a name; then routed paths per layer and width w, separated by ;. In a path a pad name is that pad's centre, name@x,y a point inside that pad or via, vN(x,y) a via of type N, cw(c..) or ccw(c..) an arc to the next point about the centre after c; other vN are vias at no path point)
ADDR: IC102.34 pad.@72.1,41 R137.1 R139.2
ALERT: CN102.2 IC102.20 pad.@50.95,26.5 pad.@74.7,31.1 R125.2 TP122.1 | length 32.9
  TOP w0.5: pad.@50.95,26.5 51.121,26.671 CN102.2@51.121,29.217
  BOTTOM w0.3: R125.2@50.95,27.575 pad.@50.95,26.5 54.35,23.1 TP122.1@59.75,23.1 60.2,23.1 64.9,27.8 69.75,27.8 70.05,28.1 70.7,28.1 71.55,28.95 71.55,29.921 72.729,31.1 pad.@74.7,31.1
BIAS: C143.1 D102.A D107.A IC102.29 pad.@77.6,38.1 R139.1 TP119.1 | length 2.2
  TOP w0.2: IC102.29@72.898,37.5 73.25,37.5 73.6,37.85 74.3,37.85
  TOP w0.3: 74.3,37.85 74.743,38.293
BST1: C117.1 D102.C IC102.1 pad.@66.3,39.65
BST2: C120.1 D107.C IC102.36 pad.@70.3,41
CSN1: pad.@62.1,44.8 Q103.5 R104.2 R123.2 TP103.1 | length 4.1
  TOP w0.2: R104.2@60.05,44.55 60.45,44.55 60.9,45 61.9,45 pad.@62.1,44.8
  BOTTOM w0.3: R123.2@61.85,43.075 61.85,43.58 62.1,43.83 pad.@62.1,44.8
  other v2: 58.9,46.05 59.75,46.05 60.6,46.05 58.05,49.6 58.9,49.6 59.75,49.6 60.6,49.6
CSN2: C134.2 C135.2 L103.1 pad.@77.45,40.4 pad.@91.7,44.25 R106.2 R119.2 R132.1 | length 19.7
  TOP w0.2: pad.@91.7,44.25 92,44.25 92,44.2 92.4,43.8 92.9,43.8 R106.2@93,43.9
  BOTTOM w0.2: pad.@91.7,44.25 pad.@91.85,44.25
  BOTTOM w0.3: pad.@77.45,40.4 77.99,40.4 78.29,40.7 90.4,40.7 92.5,42.8 92.5,43.95 92.2,44.25 pad.@91.85,44.25
CSP1: C103.2 C104.2 C107.2 C108.2 C109.2 C112.2 C113.2 C114.2 FL101.1 pad.@57.2,43.55 pad.@57.2,44.55 pad.@61.25,44.3 Q102.5 R104.1 R124.2 | length 3.7
  TOP w0.2: R104.1@60.1,43.8 60.185,43.8 60.485,44.1 61.05,44.1 pad.@61.25,44.3
  BOTTOM w0.3: R124.2@60.85,43.075 60.85,43.9 pad.@61.25,44.3
  BOTTOM w0.8: pad.@57.2,43.55 pad.@57.2,44.55
  other v1: 54.4,44.55 55.3,44.55 53.3,45.45 54.2,45.45 55.1,45.45 56,45.45 53.3,46.35 54.2,46.35 55.1,46.35 56,46.35 56.9,46.35 53.3,47.25 54.2,47.25 55.1,47.25 56,47.25 56.9,47.25 53.3,48.15 54.2,48.15 55.1,48.15 56,48.15 56.9,48.15 53.3,49.05 54.2,49.05 55.1,49.05 56,49.05 56.9,49.05 53.3,49.95 54.2,49.95 55.1,49.95 56,49.95 56.9,49.95
CSP2: C119.1 Q105.5 R105.1 R130.1 TP108.1 | length 4.3
  TOP w0.2: R105.1@76.6,42.883 R105.1@76.6,43.7 R105.1@76.849,43.451
  TOP w0.3: R130.1@75.375,41.15 76.16,41.15 77.108,42.097 77.108,42.389 76.607,42.89 R105.1@76.6,42.883
  other v2: 71.9,42.15 75.4,42.6 71.9,43 75.4,43.45 71.9,43.85 75.4,44.3 71.9,44.7
DH1: D103.C IC102.40 pad.@67.3,39.95 R102.2
DH1_Q: Q103.4 R102.1 R103.1 R108.2 TP104.1 | length 4.4
  BOTTOM w0.5: TP104.1@61.788,50.098 61.793,50.093 62.686,49.2 R103.1@62.825,49.2 62.825,48.702 63.877,47.65 R102.1@64.86,47.65
DH2: D105.C IC102.37 pad.@69.45,40.6 R115.2
DH2_Q: Q105.4 R111.2 R113.1 R115.1 TP109.1 | length 0.1
  TOP w0.2: TP109.1@70.375,45.625 TP109.1@70.45,45.7
DL1: D104.C IC102.2 pad.@66,38.55 R101.2
DL1_Q: Q104.4 R101.1 R107.1 R109.2 TP106.1
DL2: D106.C IC102.35 pad.@71.2,41 R116.2
DL2_Q: Q106.4 R112.2 R114.1 R116.1 TP111.1 | length 13.3
  BOTTOM w0.5: R116.1@72.706,45.879 73.611,45.879 73.683,45.808 73.78,45.711 75.681,45.711 76.147,46.177 78.725,46.177 79.45,46.902 TP111.1@79.45,51.7 ; R116.1@72.706,45.907 R114.1@73.871,45.907
GDRV: IC102.8 Q107.4 R120.2 TP114.1 | length 36.8
  Mid-Layer 2 w0.3: v1(65.5,34) 66.35,33.15 66.35,31.65 66,31.3 66,29.2 68.25,26.95 89.65,26.95 91.75,24.85 91.75,22.776 TP114.1@90.437,21.463
GND_A: C139.1 C140.1 C141.1 C142.2 C143.2 C145.2 C146.2 C149.1 C150.1 C151.1 C152.1 C153.1 C154.1 CN102.1T CN102.2T CN102.5 IC102.23 IC102.26 pad.@57.45,27.15 pad.@58.45,27.15 R129.2 R135.2 R137.2 R141.1 TP118.1 | length 8.7
  TOP w0.2: IC102.23@72.898,34.5 73.55,34.5 74.6,33.45
  BOTTOM w0.3: 76.75,31.6 C152.1@76.75,32.325 ; C153.1@79.27,37.981 82.046,37.981 ; R141.1@81.017,34.24 82.292,34.24 ; C154.1@81.024,36.972 81.899,36.972 ; R137.2@81.11,39.039 81.981,39.039
  other v1: 72.9,28.7 68.875,28.725 75.75,31.55 108.5,37.5 108.5,39 108.5,40.5 108.5,42 108.5,43.5
GND_P: C102.1 C103.1 C104.1 C106.1 C107.1 C108.1 C109.1 C111.1 C112.1 C113.1 C114.1 C116.1 C118.1 C119.2 C122.1 C123.1 C124.1 C125.1 C126.1 C127.1 C128.1 C129.1 C130.1 C131.1 C132.1 C133.1 C134.1 C135.1 C136.1 C137.1 C138.1 CN101.1T CN101.2 CN101.2T CN101.3T CN101.4T D101.A IC101.2 IC101.5 IC102.3 IC102.41 Q104.1 Q104.2 Q104.3 Q106.1 Q106.2 Q106.3 Q107.1 Q107.2 Q107.3 R109.1 R112.1 R119.1 R120.1 R129.1 TP107.1 TP112.1 TP116.1 TP131.1 TP132.1 TP133.1 TP134.1 | length 97.7
  TOP w0.2: IC102.3@67.002,37 67.5,37 67.6,36.9 67.6,36.65 67.7,36.55 69.15,36.55 IC102.41@69.95,35.75
  TOP w0.3: 87.9,21.503 R120.1@88.626,21.503 88.626,22.25
  TOP w1: 22.93,31.76 CN101.1T@22.93,30.535 CN101.2T@25.23,30.535 ; 22.93,48.34 CN101.4T@22.93,49.565 CN101.3T@25.23,49.565 ; 25.23,29.31 CN101.2T@25.23,30.535 ; 25.23,31.76 CN101.2T@25.23,30.535 ; 25.23,48.34 CN101.3T@25.23,49.565 ; 25.23,50.79 CN101.3T@25.23,49.565 ; 26.455,30.535 CN101.2T@25.23,30.535 ; 26.455,49.565 CN101.3T@25.23,49.565
  TOP w2.032: 33.75,43.3 CN101.2@36.3,43.3 ; 36.3,45.85 CN101.2@36.3,43.3 ; 38.85,43.3 CN101.2@36.3,43.3
  Mid-Layer 1 w1: 22.93,32.01 CN101.1T@22.93,30.535 CN101.2T@25.23,30.535 ; 22.93,48.057 CN101.4T@22.93,49.565 CN101.3T@25.23,49.565 ; 25.23,29.06 CN101.2T@25.23,30.535 ; 25.23,32.01 CN101.2T@25.23,30.535 ; 25.23,48.09 CN101.3T@25.23,49.565 ; 25.23,51.04 CN101.3T@25.23,49.565 ; 26.705,30.535 CN101.2T@25.23,30.535 ; 26.705,49.565 CN101.3T@25.23,49.565
  Mid-Layer 1 w2.032: 34,43.3 CN101.2@36.3,43.3 ; CN101.2@36.3,41.6 CN101.2@36.3,43.3 ; 36.3,45.6 CN101.2@36.3,43.3 ; 38.6,43.3 CN101.2@36.3,43.3
  Mid-Layer 2 w1: 22.93,32.01 CN101.1T@22.93,30.535 CN101.2T@25.23,30.535 ; 22.93,47.973 CN101.4T@22.93,49.565 CN101.3T@25.23,49.565 ; 25.23,29.06 CN101.2T@25.23,30.535 ; 25.23,32.01 CN101.2T@25.23,30.535 ; 25.23,47.973 CN101.3T@25.23,49.565 ; 25.23,51.04 CN101.3T@25.23,49.565 ; 26.705,30.535 CN101.2T@25.23,30.535 ; 26.705,49.565 CN101.3T@25.23,49.565
  Mid-Layer 2 w2.032: 34,43.3 CN101.2@36.3,43.3 ; CN101.2@36.3,41.65 CN101.2@36.3,43.3 ; 36.3,45.6 CN101.2@36.3,43.3 ; 38.6,43.3 CN101.2@36.3,43.3
  BOTTOM w0.3: 51.475,35.8 IC101.2@51.475,37.425
  BOTTOM w1: 22.93,31.76 CN101.1T@22.93,30.535 CN101.2T@25.23,30.535 ; 22.93,48.34 CN101.4T@22.93,49.565 CN101.3T@25.23,49.565 ; 25.23,29.31 CN101.2T@25.23,30.535 ; 25.23,31.76 CN101.2T@25.23,30.535 ; 25.23,48.34 CN101.3T@25.23,49.565 ; 25.23,50.79 CN101.3T@25.23,49.565 ; 26.455,30.535 CN101.2T@25.23,30.535 ; 26.455,49.565 CN101.3T@25.23,49.565
  BOTTOM w2.032: 34.15,43.3 CN101.2@36.3,43.3 36.3,45.45
  other v1: 27.6,21.35 29.6,21.35 31.6,21.35 33.05,21.35 34.8,21.35 38.8,21.35 40,21.35 61.75,21.5 64.25,21.5 66.75,21.5 69.25,21.5 71.75,21.5 74.25,21.5 76.75,21.5 77.8,21.8 78.7,21.8 79.6,21.8 80.5,21.8 81.4,21.8 82.3,21.8 83.2,21.8 84.1,21.8 85,21.8 85.9,21.8 86.8,21.8 87.7,21.8 77.8,22.7 78.7,22.7 79.6,22.7 80.5,22.7 81.4,22.7 82.3,22.7 83.2,22.7 84.1,22.7 85,22.7 85.9,22.7 86.8,22.7 87.7,22.7 77.8,23.6 78.7,23.6 79.6,23.6 80.5,23.6 81.4,23.6 82.3,23.6 83.2,23.6 84.1,23.6 85,23.6 85.9,23.6 86.8,23.6 87.7,23.6 27.6,23.85 29.6,23.85 77.8,24.5 78.7,24.5 79.6,24.5 80.5,24.5 81.4,24.5 82.3,24.5 83.2,24.5 84.1,24.5 85,24.5 85.9,24.5 86.8,24.5 87.7,24.5 77.8,25.4 78.7,25.4 79.6,25.4 80.5,25.4 81.4,25.4 82.3,25.4 83.2,25.4 84.1,25.4 85,25.4 85.9,25.4 86.8,25.4 87.7,25.4 26.4,27.95 28.9,27.95 80.5,29 81.4,29 82.3,29 83.2,29 84.1,29 85,29 88.5,29 89.4,29 90.3,29 91.2,29 92.1,29 93,29 55.25,32.25 56.15,32.25 57.05,32.25 57.95,32.25 21.4,32.95 23.9,32.95 26.4,32.95 28.9,32.95 54.35,33.15 55.25,33.15 56.15,33.15 57.05,33.15 57.95,33.15 54.35,34.05 55.25,34.05 56.15,34.05 57.05,34.05 57.95,34.05 54.35,34.95 55.25,34.95 56.15,34.95 57.05,34.95 57.95,34.95 21.4,35.45 23.9,35.45 26.4,35.45 28.9,35.45 54.35,35.85 55.25,35.85 56.15,35.85 57.05,35.85 57.95,35.85 54.35,36.75 55.25,36.75 56.15,36.75 57.05,36.75 57.95,36.75 65.25,37.25 64.5,37.7 21.4,37.95 23.9,37.95 26.4,37.95 28.9,37.95 21.4,40.45 23.9,40.45 26.4,40.45 28.9,40.45 31.4,40.45 21.4,42.95 23.9,42.95 26.4,42.95 28.9,42.95 31.4,42.95 21.4,45.45 23.9,45.45 26.4,45.45 28.9,45.45 31.4,45.45 33.9,45.45 81.25,46 82.15,46 83.05,46 83.95,46 84.85,46 85.75,46 86.65,46 87.55,46 38.9,46.3 81.25,46.9 82.15,46.9 83.05,46.9 83.95,46.9 84.85,46.9 85.75,46.9 86.65,46.9 87.55,46.9 39.9,47.1 81.25,47.8 82.15,47.8 83.05,47.8 83.95,47.8 84.85,47.8 85.75,47.8 86.65,47.8 87.55,47.8 21.4,47.95 23.9,47.95 26.4,47.95 28.9,47.95 31.4,47.95 33.9,47.95 38.9,47.95 40.7,47.95 81.25,48.7 82.15,48.7 83.05,48.7 83.95,48.7 84.85,48.7 85.75,48.7 86.65,48.7 87.55,48.7 41.55,48.75 38.9,49.55 40.7,49.55 42.3,49.55 81.25,49.6 82.15,49.6 83.05,49.6 83.95,49.6 84.85,49.6 85.75,49.6 86.65,49.6 87.55,49.6 43.2,50.35 31.4,51.1 33.9,51.1 36.4,51.1 38.9,51.1 41.4,51.1 43.9,51.1 31.4,53.6 33.9,53.6 36.4,53.6 38.9,53.6 41.4,53.6 81.25,55.8 82.15,55.8 83.05,55.8 83.95,55.8 84.85,55.8 85.75,55.8 86.65,55.8 87.55,55.8 88.45,55.8 91.5,55.8 92.4,55.8 93.3,55.8 94.2,55.8 95.1,55.8 96,55.8 96.9,55.8 97.8,55.8 98.7,55.8 43.9,56.1 81.25,56.7 82.15,56.7 83.05,56.7 83.95,56.7 84.85,56.7 85.75,56.7 86.65,56.7 87.55,56.7 88.45,56.7 91.5,56.7 92.4,56.7 93.3,56.7 94.2,56.7 95.1,56.7 96,56.7 96.9,56.7 97.8,56.7 98.7,56.7 81.25,57.6 82.15,57.6 83.05,57.6 83.95,57.6 84.85,57.6 85.75,57.6 86.65,57.6 87.55,57.6 88.45,57.6 91.5,57.6 92.4,57.6 93.3,57.6 94.2,57.6 95.1,57.6 96,57.6 96.9,57.6 97.8,57.6 98.7,57.6 53.75,58.5 81.25,58.5 82.15,58.5 83.05,58.5 83.95,58.5 84.85,58.5 85.75,58.5 86.65,58.5 87.55,58.5 88.45,58.5 91.5,58.5 92.4,58.5 93.3,58.5 94.2,58.5 95.1,58.5 96,58.5 96.9,58.5 97.8,58.5 98.7,58.5 31.4,58.6 33.9,58.6 36.4,58.6 38.9,58.6 41.4,58.6 43.9,58.6 46.4,58.6 48.9,58.6 51.4,58.6
  other v2: 68.3,34.1 71.6,34.1 68.3,37.4 71.6,37.4 63,38.45 63.9,38.45 63,39.35 63.9,39.35 63,40.25 63.9,40.25
HVCC1: C150.2 CN103.7 IC102.25 | length 37.1
  TOP w0.3: CN103.7@100.735,43 100.835,42.9 v1(103.45,42.9)
  Mid-Layer 2 w0.3: v1(74.8,35.1) 95.65,35.1 v1(103.45,42.9)
  BOTTOM w0.3: v1@103.45,42.864 C150.2@104.667,42.864 104.631,42.9 v1(103.45,42.9)
HVCC2: C149.2 CN103.6 IC102.24 | length 35.3
  TOP w0.3: CN103.6@100.735,41 v1(103.45,41)
  Mid-Layer 2 w0.3: v1(74.8,34.2) 75.939,34.2 76.289,34.55 95.856,34.55 102.306,41 v1(103.45,41)
  BOTTOM w0.3: v1(103.45,41) 104.572,41 C149.2@104.594,41.022
HVDM: CN103.5 IC102.21 | length 35.1
  TOP w0.3: CN103.5@100.735,39 v1(103.45,39)
  Mid-Layer 2 w0.3: v1(73.65,32.85) 74.45,32.85 74.52,32.92 97.37,32.92 v1(103.45,39)
HVDP: CN103.4 IC102.22 | length 33.5
  TOP w0.3: CN103.4@100.735,37 v1(103.45,37)
  Mid-Layer 2 w0.3: v1(74.7,32.1) 74.925,32.325 97.482,32.325 102.157,37 v1(103.45,37)
HVEN: IC102.6 pad.@65.5,35.35 R134.2 R135.1 | length 8
  BOTTOM w0.3: pad.@65.5,35.35 67.6,33.25 68.6,33.25 70.425,31.425 R134.2@70.425,30.95 70.425,30.1 R135.1@70.5,30.025
LX1: C117.2 IC102.39 L102.1 Q103.1 Q103.2 Q103.3 Q104.5 R108.1 TP105.1 | length 9
  Mid-Layer 1 w0.5: TP105.1@62.9,47.05 67.3,47.05 67.8,46.55 67.8,43.15 v1(67.45,42.8)
  other v2: 63.25,43.5 66.75,43.5 63.25,44.35 66.75,44.35 63.25,45.2 66.75,45.2 63.25,46.05 66.75,46.05
LX2: C120.2 IC102.38 L102.2 Q105.1 Q105.2 Q105.3 Q106.5 R111.1 TP110.1 | length 11.3
  TOP w0.5: R111.1@69.91,43.56 R111.1@69.91,43.817
  Mid-Layer 1 w0.5: v1(69.15,42.8) 69.15,45.819 69.972,46.641 ; 71.907,46.65 69.981,46.65 69.972,46.641 ; 74.848,46.641 69.972,46.641
  other v2: 75.8,47.4 76.65,47.4 77.5,47.4 78.35,47.4 75.8,50.9 76.65,50.9 77.5,50.9 78.35,50.9
OUT: C123.2 C124.2 C125.2 C126.2 C127.2 C128.2 C129.2 C130.2 C131.2 C132.2 C133.2 pad.@77.45,41.3 pad.@91.7,43.2 R105.2 R106.1 R131.1 | length 17.6
  TOP w0.2: pad.@91.7,43.2 92.15,43.2 92.294,43.344 92.663,43.344 93.206,42.8 R106.1@94,42.8
  BOTTOM w0.3: pad.@77.45,41.3 89.8,41.3 pad.@91.7,43.2
SCL: CN102.3 pad.@52.8,26.55 R122.2 R127.2 | length 9.6
  TOP w0.5: pad.@52.8,26.55 53.121,26.871 CN102.3@53.121,29.217
  BOTTOM w0.3: R122.2@52.8,27.575 pad.@52.8,26.55 54.85,24.5 R127.2@57.725,24.5
SDA: CN102.4 pad.@54.6,26.55 R121.2 R128.2 | length 7.5
  TOP w0.5: pad.@54.6,26.55 55.121,27.071 CN102.4@55.121,29.217
  BOTTOM w0.3: R121.2@54.6,27.575 pad.@54.6,26.55 55.45,25.7 R128.2@57.825,25.7
SHLD_SNS: C138.2 CN103.1 CN103.1T CN103.2 CN103.2T CN103.3 IC102.7 Q107.5 TP115.1 | length 38.3
  TOP w0.2: v1(64.45,34) 65.15,34.7 66.2,34.7 66.5,35 IC102.7@67.002,35
  Mid-Layer 2 w0.3: v1(64.45,34) 64.45,34.45 64.7,34.7 66.15,34.7 67.8,33.05 67.8,28.5 68.7,27.6 89.85,27.6 92.55,24.9
  other v1: 93.15,21.45 94.45,21.45 95.85,21.45 97.25,21.45 98.5,21.5 92.6,22.25 93.45,22.25 94.3,22.25 95.15,22.25 99.5,22.25 100.5,23.25 101.5,24.25 92.6,25.65 93.45,25.65 94.3,25.65 95.15,25.65 94.7,26.45 95.6,26.45 95.15,27.25 96.15,27.25 97.15,27.25 98.25,28 99,28.75 103.45,30.55 104.35,30.55 105.25,30.55 106.15,30.55 103.45,31.45 104.35,31.45 105.25,31.45 106.15,31.45 103.45,32.35 104.35,32.35 105.25,32.35 106.15,32.35 103.45,33.25 104.35,33.25 105.25,33.25 106.15,33.25
SIG310: C151.2 IC102.27 pad.@73.9,36.6 R133.2 | length 3.7
  BOTTOM w0.3: pad.@73.9,36.6 74.474,36.6 75.722,35.352 75.722,35.029 75.734,35.041 R133.2@76.784,35.041
SIG311: C152.2 R133.1 | length 0.8
  BOTTOM w0.3: C152.2@76.75,33.175 R133.1@76.75,34.025
SIG313: C154.2 R136.1 R138.2 | length 1.9
  BOTTOM w0.3: R138.2@79.113,36.027 79.254,36.168 R136.1@79.254,36.97 80.173,36.97 C154.2@80.174,36.972
SIG316: C155.1 R140.1 R141.2 | length 1.9
  BOTTOM w0.3: R140.1@79.275,34.251 80.156,34.251 R141.2@80.167,34.24 80.167,35.042 C155.1@80.306,35.181
SIG317: C155.2 R138.1
SIG318: C153.2 IC102.30 pad.@73.85,38.55 R136.2 R140.2 | length 9
  BOTTOM w0.3: pad.@73.85,38.55 74.2,38.2 76.191,38.2 77.149,37.242 R136.2@78.42,37.242 ; R136.2@78.404,36.97 78.404,34.273 R140.2@78.425,34.251 ; R136.2@78.42,36.853 R136.2@78.42,37.242 ; C153.2@78.42,37.981 R136.2@78.42,37.242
